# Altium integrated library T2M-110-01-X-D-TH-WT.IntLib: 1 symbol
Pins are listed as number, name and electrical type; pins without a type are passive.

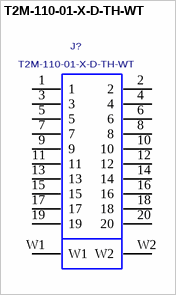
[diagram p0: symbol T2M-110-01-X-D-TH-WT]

## T2M-110-01-X-D-TH-WT
designator J?
2MM PITCH SHROUDED TERMINAL STRIP, 20 PINS.; MANUFACTURER: SAMTEC
footprint T2M-110-01-X-D-TH-WT (Footprint not found)
pins: 1, 2, 3, 4, 5, 6, 7, 8, 9, 10, 11, 12, 13, 14, 15, 16, 17, 18, 19, 20, W1, W2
